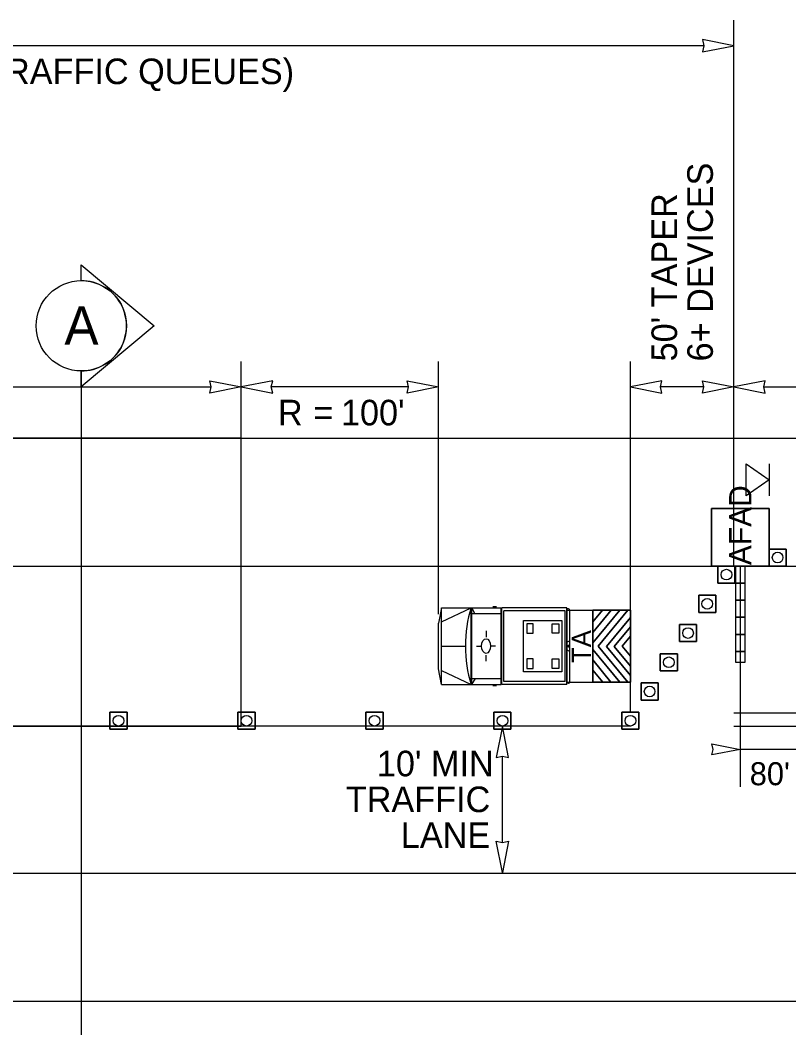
# Model space of a CAD drawing. Extents: x 99999.1 to 100095.7, y 99995 to 100010.7.
# Drawn here: x 100049.243 to 100051.645, y 100005.649 to 100008.799 of the extents above; entities that cross this region are included whole.
import ezdxf

# ---------------------------------------------------------------- set-up
doc = ezdxf.new("R2010")
doc.units = 0
for name, color, linetype in [('RD_ED_ShoulderPavedEdge', 7, 'Continuous'), ('RD_MK_LineEdgeWhite', 7, 'Continuous'), ('RD_MK_LineNoPass', 7, 'Continuous'), ('RD_MK_LineSkipCenter', 7, 'Continuous'), ('SH_TI_WZSectionCut', 7, 'Continuous'), ('TR_WZ_AFAD', 7, 'Continuous'), ('TR_WZ_PortableSignMountBlk-Wht', 7, 'Continuous'), ('TR_WZ_TrafficCone', 7, 'Continuous'), ('TR_WZ_TransportableAttenuator', 7, 'Continuous'), ('TR_WZ_WorkZoneDetails', 7, 'Continuous'), ('TR_WZ_WorkZoneTextCurrent', 7, 'Continuous')]:
    doc.layers.add(name, color=color, linetype=linetype)

msp = doc.modelspace()

# ---------------------------------------------------------------- linework, layer by layer
at = {"layer": 'RD_ED_ShoulderPavedEdge'}
for p, q in [((100040.1076, 100007.4923), (100055.6424, 100007.4923)), ((100040.1076, 100005.7323), (100055.6424, 100005.7323))]:
    msp.add_line(p, q, dxfattribs=at)
at = {"layer": 'RD_MK_LineEdgeWhite'}
for p, q in [((100040.1076, 100007.0923), (100055.6424, 100007.0923)), ((100040.1076, 100006.1323), (100055.6424, 100006.1323))]:
    msp.add_line(p, q, dxfattribs=at)
at = {"layer": 'RD_MK_LineNoPass'}
msp.add_line((100051.4733, 100006.5923), (100052.2733, 100006.5923), dxfattribs=at)
at = {"layer": 'RD_MK_LineSkipCenter'}
for points in [[(100052.2733, 100006.6323), (100051.4733, 100006.6323)], [(100051.15, 100006.5923), (100043.4767, 100006.5923)]]:
    msp.add_lwpolyline(points, dxfattribs=at)
at = {"layer": 'SH_TI_WZSectionCut'}
for p, q in [((100049.4337, 100007.9847), (100049.4337, 100008.0346)), ((100049.4337, 100008.0346), (100049.6619, 100007.8435)), ((100049.6619, 100007.8435), (100049.4337, 100007.6523)), ((100049.4337, 100007.6523), (100049.4337, 100007.7022)), ((100049.4338, 100007.7022), (100049.4338, 100005.5723))]:
    msp.add_line(p, q, dxfattribs=at)
msp.add_circle((100049.4338, 100007.8435), 0.1412, dxfattribs=at)
msp.add_arc((100049.4338, 100007.8435), 0.1412, 269.9978, 90.0022, dxfattribs=at)
at = {"layer": 'TR_WZ_AFAD'}
for p, q in [((100051.4033, 100007.0923), (100051.4033, 100007.2723)), ((100051.4033, 100007.2723), (100051.5833, 100007.2723)), ((100051.5833, 100007.2723), (100051.4033, 100007.2723)), ((100051.4033, 100007.2723), (100051.4033, 100007.0923)), ((100051.5833, 100007.2723), (100051.5833, 100007.0923)), ((100051.5833, 100007.0923), (100051.5833, 100007.2723)), ((100051.5833, 100007.0923), (100051.4033, 100007.0923)), ((100051.5, 100007.0923), (100051.4933, 100007.0923)), ((100051.5, 100007.0923), (100051.5833, 100007.0923)), ((100051.5083, 100007.0923), (100051.5, 100007.0923)), ((100051.5083, 100007.039), (100051.5083, 100007.0923)), ((100051.4783, 100007.039), (100051.4783, 100006.9857)), ((100051.5083, 100006.9857), (100051.5083, 100007.039)), ((100051.4783, 100006.9857), (100051.4783, 100006.9323)), ((100051.4783, 100006.9857), (100051.4933, 100006.9857)), ((100051.4933, 100006.9857), (100051.5083, 100006.9857)), ((100051.5083, 100006.9323), (100051.5083, 100006.9857)), ((100051.4933, 100006.9323), (100051.4783, 100006.9323)), ((100051.4783, 100006.9323), (100051.4783, 100006.879)), ((100051.5083, 100006.9323), (100051.4933, 100006.9323)), ((100051.5083, 100006.879), (100051.5083, 100006.9323)), ((100051.4783, 100006.879), (100051.4783, 100006.8257)), ((100051.4783, 100006.879), (100051.4933, 100006.879)), ((100051.4933, 100006.879), (100051.5083, 100006.879)), ((100051.5083, 100006.8257), (100051.5083, 100006.879)), ((100051.4933, 100006.8257), (100051.4783, 100006.8257)), ((100051.4783, 100006.8257), (100051.4783, 100006.7923)), ((100051.5083, 100006.8257), (100051.4933, 100006.8257))]:
    msp.add_line(p, q, dxfattribs=at)
for points in [[(100051.4033, 100007.0923), (100051.4867, 100007.0923), (100051.5, 100007.0923)], [(100051.4933, 100007.0923), (100051.4867, 100007.0923), (100051.4783, 100007.0923), (100051.4783, 100007.039)], [(100051.4783, 100007.0923), (100051.4783, 100006.7923), (100051.5083, 100006.7923), (100051.5083, 100007.0923)], [(100051.4783, 100007.039), (100051.4933, 100007.039), (100051.5083, 100007.039)], [(100051.5083, 100007.039), (100051.4933, 100007.039), (100051.4783, 100007.039)], [(100051.5083, 100006.9857), (100051.4933, 100006.9857), (100051.4783, 100006.9857)], [(100051.4783, 100006.9323), (100051.4933, 100006.9323), (100051.5083, 100006.9323)], [(100051.5083, 100006.879), (100051.4933, 100006.879), (100051.4783, 100006.879)], [(100051.4783, 100006.8257), (100051.4933, 100006.8257), (100051.5083, 100006.8257)], [(100051.4783, 100006.7923), (100051.5083, 100006.7923), (100051.5083, 100006.8257)]]:
    msp.add_lwpolyline(points, dxfattribs=at)
at = {"layer": 'TR_WZ_PortableSignMountBlk-Wht'}
msp.add_line((100051.5833, 100007.4123), (100051.5833, 100007.3123), dxfattribs=at)
msp.add_lwpolyline([(100051.5833, 100007.3624), (100051.5115, 100007.3123), (100051.5115, 100007.4123)], close=True, dxfattribs=at)
at = {"layer": 'TR_WZ_TrafficCone'}
for points in [[(100051.6367, 100007.0923), (100051.5833, 100007.0923), (100051.5833, 100007.1457), (100051.6367, 100007.1457), (100051.6367, 100007.0923)], [(100051.6367, 100007.1457), (100051.5833, 100007.1457), (100051.5833, 100007.0923), (100051.6367, 100007.0923), (100051.6367, 100007.1457)], [(100051.4766, 100007.0923), (100051.4233, 100007.0923), (100051.4233, 100007.039), (100051.4766, 100007.039), (100051.4766, 100007.0923)], [(100051.4766, 100007.039), (100051.4233, 100007.039), (100051.4233, 100007.0923), (100051.4766, 100007.0923), (100051.4766, 100007.039)], [(100051.4166, 100007.001), (100051.3633, 100007.001), (100051.3633, 100006.9477), (100051.4166, 100006.9477), (100051.4166, 100007.001)], [(100051.4166, 100006.9477), (100051.3633, 100006.9477), (100051.3633, 100007.001), (100051.4166, 100007.001), (100051.4166, 100006.9477)], [(100051.3566, 100006.9097), (100051.3033, 100006.9097), (100051.3033, 100006.8563), (100051.3566, 100006.8563), (100051.3566, 100006.9097)], [(100051.3566, 100006.8563), (100051.3033, 100006.8563), (100051.3033, 100006.9097), (100051.3566, 100006.9097), (100051.3566, 100006.8563)], [(100051.2966, 100006.8183), (100051.2433, 100006.8183), (100051.2433, 100006.765), (100051.2966, 100006.765), (100051.2966, 100006.8183)], [(100051.2966, 100006.765), (100051.2433, 100006.765), (100051.2433, 100006.8183), (100051.2966, 100006.8183), (100051.2966, 100006.765)], [(100051.2366, 100006.727), (100051.1833, 100006.727), (100051.1833, 100006.6737), (100051.2366, 100006.6737), (100051.2366, 100006.727)], [(100051.2366, 100006.6737), (100051.1833, 100006.6737), (100051.1833, 100006.727), (100051.2366, 100006.727), (100051.2366, 100006.6737)], [(100049.5234, 100006.6357), (100049.5767, 100006.6357), (100049.5767, 100006.5823), (100049.5234, 100006.5823), (100049.5234, 100006.6357)], [(100049.5234, 100006.5823), (100049.5767, 100006.5823), (100049.5767, 100006.6357), (100049.5234, 100006.6357), (100049.5234, 100006.5823)], [(100049.9234, 100006.6357), (100049.9767, 100006.6357), (100049.9767, 100006.5823), (100049.9234, 100006.5823), (100049.9234, 100006.6357)], [(100049.9234, 100006.5823), (100049.9767, 100006.5823), (100049.9767, 100006.6357), (100049.9234, 100006.6357), (100049.9234, 100006.5823)], [(100050.3234, 100006.6357), (100050.3767, 100006.6357), (100050.3767, 100006.5823), (100050.3234, 100006.5823), (100050.3234, 100006.6357)], [(100050.3234, 100006.5823), (100050.3767, 100006.5823), (100050.3767, 100006.6357), (100050.3234, 100006.6357), (100050.3234, 100006.5823)], [(100050.7234, 100006.6357), (100050.7767, 100006.6357), (100050.7767, 100006.5823), (100050.7234, 100006.5823), (100050.7234, 100006.6357)], [(100050.7234, 100006.5823), (100050.7767, 100006.5823), (100050.7767, 100006.6357), (100050.7234, 100006.6357), (100050.7234, 100006.5823)], [(100051.1766, 100006.6357), (100051.1233, 100006.6357), (100051.1233, 100006.5823), (100051.1766, 100006.5823), (100051.1766, 100006.6357)], [(100051.1766, 100006.5823), (100051.1233, 100006.5823), (100051.1233, 100006.6357), (100051.1766, 100006.6357), (100051.1766, 100006.5823)]]:
    msp.add_lwpolyline(points, dxfattribs=at)
for centre in [(100051.61, 100007.119), (100051.45, 100007.0657), (100051.39, 100006.9743), (100051.33, 100006.883), (100051.27, 100006.7917), (100051.21, 100006.7003), (100049.55, 100006.609), (100049.95, 100006.609), (100050.35, 100006.609), (100050.75, 100006.609), (100051.15, 100006.609)]:
    msp.add_circle(centre, 0.0167, dxfattribs=at)
at = {"layer": 'TR_WZ_TransportableAttenuator'}
for p, q in [((100050.5592, 100006.9623), (100050.55, 100006.9138)), ((100050.5592, 100006.7223), (100050.5592, 100006.9623)), ((100050.5592, 100006.9623), (100050.7457, 100006.9623)), ((100050.5592, 100006.9183), (100050.6525, 100006.9623)), ((100050.6525, 100006.7223), (100050.6525, 100006.9623)), ((100050.6541, 100006.7223), (100050.6541, 100006.9623)), ((100050.664, 100006.9437), (100050.6541, 100006.9623)), ((100050.7203, 100006.9656), (100050.7315, 100006.9656)), ((100050.7457, 100006.7223), (100050.7457, 100006.9623)), ((100050.9516, 100006.9623), (100050.7484, 100006.9623)), ((100050.7484, 100006.7223), (100050.7484, 100006.9623)), ((100050.9516, 100006.7223), (100050.9516, 100006.9623)), ((100050.9516, 100006.9546), (100051.0321, 100006.9546)), ((100050.9516, 100006.7298), (100050.9516, 100006.9546)), ((100050.9567, 100006.9583), (100050.9523, 100006.9583)), ((100050.9523, 100006.7262), (100050.9523, 100006.9583)), ((100051.0321, 100006.8522), (100051.1173, 100006.9548)), ((100051.0321, 100006.9185), (100051.0628, 100006.9548)), ((100051.0897, 100006.9548), (100051.0321, 100006.8853)), ((100051.1173, 100006.9548), (100051.0321, 100006.8522)), ((100051.0321, 100006.8853), (100051.0897, 100006.9548)), ((100051.0628, 100006.9548), (100051.0321, 100006.9185)), ((100051.0321, 100006.9546), (100051.0321, 100006.7294)), ((100051.1423, 100006.9548), (100051.0487, 100006.842)), ((100051.0487, 100006.842), (100051.1423, 100006.9548)), ((100051.0628, 100006.9548), (100051.0897, 100006.9548)), ((100051.0897, 100006.9548), (100051.0628, 100006.9548)), ((100051.1173, 100006.9548), (100051.1423, 100006.9548)), ((100051.1423, 100006.9548), (100051.1173, 100006.9548)), ((100050.6541, 100006.9437), (100050.7457, 100006.9437)), ((100050.9458, 100006.9527), (100050.7542, 100006.9527)), ((100050.7542, 100006.7318), (100050.7542, 100006.9527)), ((100050.9458, 100006.7318), (100050.9458, 100006.9527)), ((100050.9611, 100006.7335), (100050.9611, 100006.951)), ((100051.0749, 100006.8414), (100051.15, 100006.9319)), ((100051.15, 100006.9319), (100051.0749, 100006.8414)), ((100051.15, 100006.9319), (100051.15, 100006.9025)), ((100051.15, 100006.9025), (100051.15, 100006.9319)), ((100050.55, 100006.7707), (100050.55, 100006.9138)), ((100051.0321, 100006.8853), (100051.0321, 100006.9185)), ((100051.0321, 100006.9185), (100051.0321, 100006.8853)), ((100051.15, 100006.9025), (100051.099, 100006.8411)), ((100051.099, 100006.8411), (100051.15, 100006.9025)), ((100050.6989, 100006.8898), (100050.6989, 100006.8704)), ((100050.9611, 100006.8592), (100050.9523, 100006.8547)), ((100051.1239, 100006.8419), (100051.15, 100006.8733)), ((100051.15, 100006.8733), (100051.1239, 100006.8419)), ((100051.15, 100006.8733), (100051.15, 100006.8109)), ((100051.15, 100006.8109), (100051.15, 100006.8733)), ((100050.5592, 100006.8423), (100050.6341, 100006.8423)), ((100050.6691, 100006.8421), (100050.6816, 100006.8422)), ((100050.7128, 100006.8427), (100050.7128, 100006.8427)), ((100050.7287, 100006.8421), (100050.7162, 100006.8422)), ((100050.9611, 100006.8254), (100050.9523, 100006.8299)), ((100050.9587, 100006.8423), (100050.9546, 100006.8423)), ((100050.9567, 100006.8389), (100050.9567, 100006.8456)), ((100051.0321, 100006.8321), (100051.0321, 100006.8522)), ((100051.0321, 100006.8522), (100051.0321, 100006.8321)), ((100051.1167, 100006.7294), (100051.0321, 100006.8321)), ((100051.0321, 100006.8321), (100051.1167, 100006.7294)), ((100051.0487, 100006.842), (100051.1422, 100006.7294)), ((100051.1422, 100006.7294), (100051.0487, 100006.842)), ((100051.15, 100006.7508), (100051.0749, 100006.8414)), ((100051.0749, 100006.8414), (100051.15, 100006.7508)), ((100051.099, 100006.8411), (100051.15, 100006.78)), ((100051.15, 100006.78), (100051.099, 100006.8411)), ((100051.15, 100006.8109), (100051.1239, 100006.8419)), ((100051.1239, 100006.8419), (100051.15, 100006.8109)), ((100050.6989, 100006.7947), (100050.6989, 100006.8141)), ((100051.0321, 100006.7989), (100051.0891, 100006.7294)), ((100051.0321, 100006.7675), (100051.0321, 100006.7989)), ((100051.0891, 100006.7294), (100051.0321, 100006.7989)), ((100051.0321, 100006.7989), (100051.0321, 100006.7675)), ((100050.5592, 100006.7223), (100050.55, 100006.7707)), ((100050.5592, 100006.7662), (100050.6525, 100006.7223)), ((100051.0637, 100006.7294), (100051.0321, 100006.7675)), ((100051.0321, 100006.7675), (100051.0637, 100006.7294)), ((100051.15, 100006.78), (100051.15, 100006.7508)), ((100051.15, 100006.7508), (100051.15, 100006.78)), ((100050.6541, 100006.7223), (100050.666, 100006.7409)), ((100050.6541, 100006.7409), (100050.7457, 100006.7409)), ((100050.5592, 100006.7223), (100050.7457, 100006.7223)), ((100050.7203, 100006.7189), (100050.7315, 100006.7189)), ((100050.9516, 100006.7223), (100050.7484, 100006.7223)), ((100050.9458, 100006.7318), (100050.7542, 100006.7318)), ((100050.9516, 100006.7294), (100051.0321, 100006.7294)), ((100050.9567, 100006.7262), (100050.9523, 100006.7262)), ((100051.0891, 100006.7294), (100051.0637, 100006.7294)), ((100051.0637, 100006.7294), (100051.0891, 100006.7294)), ((100051.1422, 100006.7294), (100051.1167, 100006.7294)), ((100051.1167, 100006.7294), (100051.1422, 100006.7294))]:
    msp.add_line(p, q, dxfattribs=at)
for points in [[(100051.0321, 100006.9548), (100051.15, 100006.9548), (100051.15, 100006.7294), (100051.0321, 100006.7294)], [(100050.9358, 100006.7623), (100050.8158, 100006.7623), (100050.8158, 100006.9223), (100050.9358, 100006.9223)], [(100050.8258, 100006.8823), (100050.8458, 100006.8823), (100050.8458, 100006.9123), (100050.8258, 100006.9123)], [(100050.9258, 100006.8823), (100050.9058, 100006.8823), (100050.9058, 100006.9123), (100050.9258, 100006.9123)], [(100050.8258, 100006.7723), (100050.8458, 100006.7723), (100050.8458, 100006.8023), (100050.8258, 100006.8023)], [(100050.9258, 100006.7723), (100050.9058, 100006.7723), (100050.9058, 100006.8023), (100050.9258, 100006.8023)]]:
    msp.add_lwpolyline(points, close=True, dxfattribs=at)
msp.add_lwpolyline([(100051.0321, 100006.7294), (100051.15, 100006.7294), (100051.15, 100006.9548), (100051.0321, 100006.9546)], dxfattribs=at)
for centre, major_axis, start_param, end_param in [((100050.7857, 100006.8423), (0, -0.2519), 4.215852, 5.209111), ((100050.9567, 100006.951), (0, 0.00732), 4.712389, 6.283185), ((100050.9567, 100006.7335), (0, -0.00732), 6.283185, 7.853982)]:
    msp.add_ellipse(centre, major_axis=major_axis, ratio=0.60201, start_param=start_param, end_param=end_param, dxfattribs=at)
for centre, major_axis in [((100050.6989, 100006.8423), (0, 0.0231)), ((100050.9567, 100006.8423), (0, 0.00338))]:
    msp.add_ellipse(centre, major_axis=major_axis, ratio=0.60201, dxfattribs=at)
at = {"layer": 'TR_WZ_WorkZoneDetails'}
for p, q in [((100051.4733, 100007.0923), (100051.4733, 100008.7991)), ((100051.3796, 100008.7191), (100044.3704, 100008.7191)), ((100049.9338, 100007.4923), (100049.9338, 100007.7323)), ((100050.5501, 100006.9423), (100050.5501, 100007.7323)), ((100051.15, 100006.6357), (100051.15, 100007.7323)), ((100045.2437, 100007.6523), (100049.84, 100007.6523)), ((100050.4563, 100007.6523), (100050.0275, 100007.6523)), ((100051.3796, 100007.6523), (100051.2437, 100007.6523)), ((100051.5671, 100007.6523), (100052.1296, 100007.6523)), ((100051.4933, 100007.0923), (100051.4933, 100006.4023)), ((100051.6733, 100006.5193), (100051.4933, 100006.5193)), ((100050.75, 100006.2278), (100050.75, 100006.4986))]:
    msp.add_line(p, q, dxfattribs=at)
for points in [[(100051.4733, 100008.7191), (100051.3751, 100008.7384), (100051.3796, 100008.7191), (100051.3751, 100008.6998)], [(100049.9338, 100007.6523), (100049.8355, 100007.6331), (100049.84, 100007.6523), (100049.8355, 100007.6716)], [(100049.9338, 100007.6523), (100050.032, 100007.6331), (100050.0275, 100007.6523), (100050.032, 100007.6716)], [(100050.5501, 100007.6523), (100050.4518, 100007.6331), (100050.4563, 100007.6523), (100050.4518, 100007.6716)], [(100051.15, 100007.6523), (100051.2483, 100007.6331), (100051.2437, 100007.6523), (100051.2483, 100007.6716)], [(100051.4733, 100007.6523), (100051.3751, 100007.6331), (100051.3796, 100007.6523), (100051.3751, 100007.6716)], [(100051.4733, 100007.6523), (100051.5716, 100007.6331), (100051.5671, 100007.6523), (100051.5716, 100007.6716)], [(100045.15, 100007.4923), (100045.15, 100006.5923), (100049.9338, 100006.5923), (100049.9338, 100007.4923)], [(100050.75, 100006.5923), (100050.7308, 100006.4941), (100050.75, 100006.4986), (100050.7693, 100006.4941)], [(100051.4933, 100006.5193), (100051.4049, 100006.502), (100051.409, 100006.5193), (100051.4049, 100006.5367)], [(100050.75, 100006.1341), (100050.7308, 100006.2324), (100050.75, 100006.2278), (100050.7693, 100006.2324)]]:
    msp.add_lwpolyline(points, close=True, dxfattribs=at)

# ---------------------------------------------------------------- texts
at = {"layer": 'SH_TI_WZSectionCut'}
msp.add_text('A', height=0.12, rotation=359.99, dxfattribs=at).set_placement((100049.3808, 100007.7843))
at = {"layer": 'TR_WZ_AFAD'}
msp.add_text('AFAD', height=0.07, rotation=90, dxfattribs=at).set_placement((100051.5283, 100007.0953))
at = {"layer": 'TR_WZ_TransportableAttenuator'}
msp.add_text('TA', height=0.06, rotation=90, dxfattribs=at).set_placement((100051.0266, 100006.7896))
at = {"layer": 'TR_WZ_WorkZoneTextCurrent'}
for s, height, p in [('(MINIMIZE DISTANCE BETWEEN MAINLINE FLAGGERS TO MINIMIZE DELAYS & TRAFFIC QUEUES)', 0.08, (100045.0644, 100008.5991)), ('R', 0.08, (100050.0483, 100007.5323)), ('=', 0.08, (100050.1588, 100007.5323)), ("100'", 0.08, (100050.2452, 100007.5323)), ("10' MIN", 0.08, (100050.3575, 100006.4352)), ("80'", 0.072, (100051.5229, 100006.4073)), ('TRAFFIC', 0.08, (100050.2604, 100006.3232)), ('LANE', 0.08, (100050.4323, 100006.2112))]:
    msp.add_text(s, height=height, dxfattribs=at).set_placement(p)
for s, p in [('6+ DEVICES', (100051.4077, 100007.7323)), ("50' TAPER", (100051.2957, 100007.7323))]:
    msp.add_text(s, height=0.08, rotation=90, dxfattribs=at).set_placement(p)

doc.saveas('drawing.dxf')
